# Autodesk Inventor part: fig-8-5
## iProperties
Created: 2009-04
Part Number: fig-8-5
Document SubType Name: Modeling
Designer: Sham
Density: 1 g/cm^3
Author: Sham
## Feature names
1. Extrusion1
2. Sweep3
